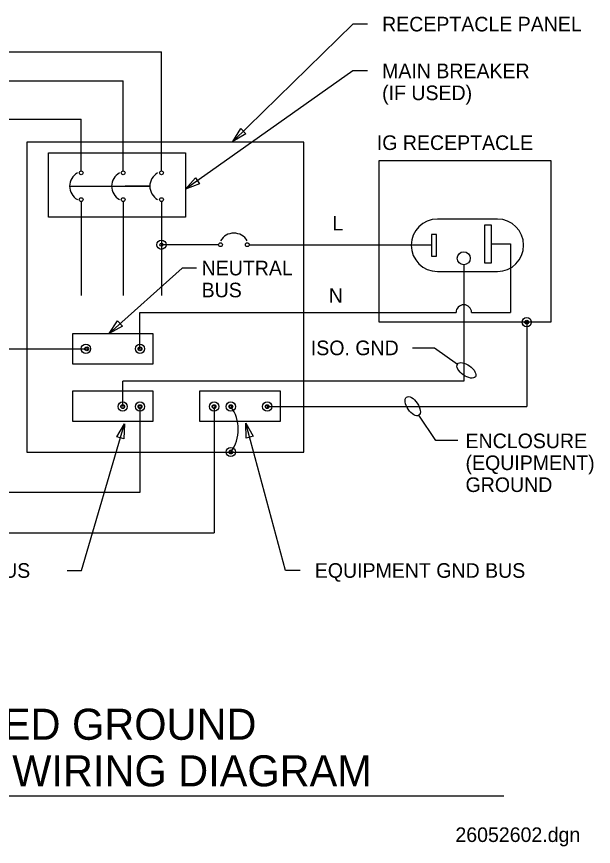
# Model space of a CAD drawing. Extents: x 10198.2 to 10245.1, y 10095.9 to 10133.7.
# Drawn here: x 10218.76 to 10245.09, y 10095.86 to 10133.72 of the extents above; entities that cross this region are included whole.
import ezdxf

# ---------------------------------------------------------------- set-up
doc = ezdxf.new("R2010")
doc.units = 0
for name, color, linetype in [('G-DETL-LINE', 7, 'Continuous'), ('G-DETL-TEXT', 7, 'Continuous'), ('G-DETL-TTXT', 7, 'Continuous')]:
    doc.layers.add(name, color=color, linetype=linetype)

msp = doc.modelspace()

# ---------------------------------------------------------------- linework, layer by layer
at = {"layer": 'G-DETL-LINE'}
for p, q in [((10212.806, 10132.117), (10225.37, 10132.117)), ((10212.806, 10132.117), (10225.37, 10132.117)), ((10225.37, 10126.681), (10225.37, 10132.117)), ((10214.725, 10130.796), (10223.625, 10130.796)), ((10214.725, 10130.796), (10223.625, 10130.796)), ((10223.625, 10126.681), (10223.625, 10130.796)), ((10223.625, 10126.681), (10223.625, 10130.796)), ((10216.47, 10129.049), (10221.706, 10129.049)), ((10216.47, 10129.049), (10221.706, 10129.049)), ((10221.706, 10126.681), (10221.706, 10129.049)), ((10221.706, 10126.681), (10221.706, 10129.049)), ((10231.867, 10127.989), (10219.225, 10127.989)), ((10219.225, 10127.989), (10219.225, 10113.856)), ((10231.867, 10127.989), (10219.225, 10127.989)), ((10219.225, 10127.989), (10219.225, 10113.856)), ((10231.867, 10113.856), (10231.867, 10127.989)), ((10231.867, 10113.856), (10231.867, 10127.989)), ((10235.305, 10127.152), (10243.142, 10127.152)), ((10235.305, 10119.781), (10235.305, 10127.152)), ((10235.305, 10127.152), (10243.142, 10127.152)), ((10235.305, 10119.781), (10235.305, 10127.152)), ((10243.142, 10127.152), (10243.142, 10119.781)), ((10243.142, 10127.152), (10243.142, 10119.781)), ((10221.177, 10125.983), (10224.841, 10125.983)), ((10221.177, 10125.983), (10222.484, 10125.983)), ((10221.177, 10125.983), (10224.841, 10125.983)), ((10221.177, 10125.983), (10222.484, 10125.983)), ((10224.841, 10125.983), (10223.715, 10125.983)), ((10224.841, 10125.983), (10223.715, 10125.983)), ((10221.706, 10125.285), (10221.706, 10120.997)), ((10221.706, 10125.285), (10221.706, 10120.997)), ((10223.625, 10125.285), (10223.625, 10120.997)), ((10223.625, 10125.285), (10223.625, 10120.997)), ((10225.37, 10125.285), (10225.37, 10120.997)), ((10240.712, 10124.486), (10237.97, 10124.486)), ((10240.712, 10124.486), (10237.97, 10124.486)), ((10240.438, 10124.212), (10240.125, 10124.212)), ((10240.125, 10124.212), (10240.125, 10122.487)), ((10240.438, 10124.212), (10240.125, 10124.212)), ((10240.125, 10124.212), (10240.125, 10122.487)), ((10240.438, 10122.487), (10240.438, 10124.212)), ((10240.438, 10122.487), (10240.438, 10124.212)), ((10237.93, 10123.781), (10237.695, 10123.781)), ((10237.695, 10123.781), (10237.695, 10122.8)), ((10237.93, 10123.781), (10237.695, 10123.781)), ((10237.695, 10123.781), (10237.695, 10122.8)), ((10237.93, 10122.8), (10237.93, 10123.781)), ((10237.93, 10122.8), (10237.93, 10123.781)), ((10227.981, 10123.315), (10225.37, 10123.315)), ((10229.377, 10123.315), (10237.695, 10123.315)), ((10240.438, 10123.349), (10241.312, 10123.349)), ((10241.312, 10123.349), (10241.312, 10120.22)), ((10237.695, 10122.8), (10237.93, 10122.8)), ((10237.695, 10122.8), (10237.93, 10122.8)), ((10240.125, 10122.487), (10240.438, 10122.487)), ((10240.125, 10122.487), (10240.438, 10122.487)), ((10237.97, 10122.095), (10240.712, 10122.095)), ((10237.97, 10122.095), (10240.712, 10122.095)), ((10239.175, 10122.402), (10239.175, 10117.092)), ((10239.175, 10122.402), (10239.175, 10117.092)), ((10224.391, 10118.568), (10224.391, 10120.22)), ((10224.391, 10120.22), (10238.82, 10120.22)), ((10239.53, 10120.22), (10241.312, 10120.22)), ((10243.142, 10119.781), (10235.305, 10119.781)), ((10243.142, 10119.781), (10235.305, 10119.781)), ((10242.049, 10119.781), (10242.049, 10115.93)), ((10242.049, 10119.781), (10242.049, 10115.93)), ((10221.318, 10119.265), (10224.982, 10119.265)), ((10221.318, 10117.869), (10221.318, 10119.265)), ((10221.318, 10119.265), (10224.982, 10119.265)), ((10221.318, 10117.869), (10221.318, 10119.265)), ((10224.982, 10119.265), (10224.982, 10117.869)), ((10224.982, 10119.265), (10224.982, 10117.869)), ((10204.262, 10118.568), (10221.921, 10118.568)), ((10224.982, 10117.869), (10221.318, 10117.869)), ((10224.982, 10117.869), (10221.318, 10117.869)), ((10239.175, 10117.092), (10223.601, 10117.092)), ((10239.175, 10117.092), (10223.601, 10117.092)), ((10223.601, 10115.93), (10223.601, 10117.092)), ((10221.318, 10115.252), (10221.318, 10116.648)), ((10221.318, 10115.252), (10221.318, 10116.648)), ((10221.318, 10116.648), (10224.982, 10116.648)), ((10224.982, 10116.648), (10224.982, 10115.252)), ((10224.982, 10116.648), (10224.982, 10115.252)), ((10227.127, 10116.648), (10230.792, 10116.648)), ((10227.127, 10115.252), (10227.127, 10116.648)), ((10230.792, 10116.648), (10230.792, 10115.252)), ((10224.391, 10115.93), (10224.391, 10112.01)), ((10224.391, 10115.93), (10224.391, 10112.01)), ((10227.774, 10115.93), (10227.774, 10110.168)), ((10227.774, 10115.93), (10227.774, 10110.168)), ((10230.2, 10115.93), (10242.049, 10115.93)), ((10230.2, 10115.93), (10242.049, 10115.93)), ((10224.982, 10115.252), (10221.318, 10115.252)), ((10230.792, 10115.252), (10227.127, 10115.252)), ((10230.792, 10115.252), (10227.127, 10115.252)), ((10219.225, 10113.856), (10231.867, 10113.856)), ((10219.225, 10113.856), (10231.867, 10113.856)), ((10224.391, 10112.01), (10204.269, 10112.01)), ((10203.479, 10110.168), (10227.774, 10110.168))]:
    msp.add_line(p, q, dxfattribs=at)
msp.add_lwpolyline([(10220.209, 10127.502), (10226.47, 10127.502), (10226.47, 10124.574), (10220.209, 10124.574)], close=True, dxfattribs=at)
msp.add_lwpolyline([(10220.209, 10127.502), (10226.47, 10127.502), (10226.47, 10124.574), (10220.209, 10124.574)], close=True, dxfattribs=at)
for centre, radius in [((10221.706, 10126.593), 0.0872), ((10221.706, 10126.593), 0.0872), ((10221.706, 10126.593), 0.0872), ((10221.706, 10126.593), 0.0872), ((10221.706, 10126.593), 0.0872), ((10221.706, 10126.593), 0.0872), ((10223.625, 10126.593), 0.0872), ((10223.625, 10126.593), 0.0872), ((10223.625, 10126.593), 0.0872), ((10223.625, 10126.593), 0.0872), ((10223.625, 10126.593), 0.0872), ((10223.625, 10126.593), 0.0872), ((10225.37, 10126.593), 0.0872), ((10225.37, 10126.593), 0.0872), ((10225.37, 10126.593), 0.0872), ((10225.37, 10126.593), 0.0872), ((10225.37, 10126.593), 0.0872), ((10225.37, 10126.593), 0.0872), ((10221.706, 10125.372), 0.0872), ((10221.706, 10125.372), 0.0872), ((10221.706, 10125.372), 0.0872), ((10221.706, 10125.372), 0.0872), ((10221.706, 10125.372), 0.0872), ((10221.706, 10125.372), 0.0872), ((10223.625, 10125.372), 0.0872), ((10223.625, 10125.372), 0.0872), ((10223.625, 10125.372), 0.0872), ((10223.625, 10125.372), 0.0872), ((10223.625, 10125.372), 0.0872), ((10223.625, 10125.372), 0.0872), ((10225.37, 10125.372), 0.0872), ((10225.37, 10125.372), 0.0872), ((10225.37, 10125.372), 0.0872), ((10225.37, 10125.372), 0.0872), ((10225.37, 10125.372), 0.0872), ((10225.37, 10125.372), 0.0872), ((10225.37, 10123.315), 0.211), ((10225.37, 10123.315), 0.211), ((10225.37, 10123.315), 0.0703), ((10225.37, 10123.315), 0.0703), ((10228.068, 10123.315), 0.0872), ((10229.289, 10123.315), 0.0872), ((10239.175, 10122.697), 0.295), ((10239.175, 10122.697), 0.295), ((10242.049, 10119.781), 0.211), ((10242.049, 10119.781), 0.211), ((10242.049, 10119.781), 0.0872), ((10242.049, 10119.781), 0.0872), ((10242.049, 10119.781), 0.0703), ((10242.049, 10119.781), 0.0703), ((10221.921, 10118.568), 0.211), ((10224.391, 10118.568), 0.211), ((10221.921, 10118.568), 0.0703), ((10221.965, 10118.568), 0.0872), ((10221.965, 10118.568), 0.0872), ((10224.391, 10118.568), 0.0872), ((10224.391, 10118.568), 0.0872), ((10224.391, 10118.568), 0.0703), ((10223.601, 10115.93), 0.211), ((10224.391, 10115.93), 0.211), ((10224.391, 10115.93), 0.211), ((10227.774, 10115.93), 0.211), ((10227.774, 10115.93), 0.211), ((10228.536, 10115.93), 0.211), ((10230.2, 10115.93), 0.211), ((10230.2, 10115.93), 0.211), ((10223.601, 10115.93), 0.0872), ((10223.601, 10115.93), 0.0872), ((10223.601, 10115.93), 0.0703), ((10224.391, 10115.93), 0.0872), ((10224.391, 10115.93), 0.0872), ((10224.391, 10115.93), 0.0703), ((10224.391, 10115.93), 0.0703), ((10227.774, 10115.93), 0.0872), ((10227.774, 10115.93), 0.0872), ((10227.774, 10115.93), 0.0703), ((10227.774, 10115.93), 0.0703), ((10228.536, 10115.93), 0.0872), ((10228.536, 10115.93), 0.0872), ((10228.536, 10115.93), 0.0703), ((10230.2, 10115.93), 0.0872), ((10230.2, 10115.93), 0.0872), ((10230.2, 10115.93), 0.0703), ((10230.2, 10115.93), 0.0703), ((10228.536, 10113.856), 0.211), ((10228.536, 10113.856), 0.0872), ((10228.536, 10113.856), 0.0872), ((10228.536, 10113.856), 0.0703)]:
    msp.add_circle(centre, radius, dxfattribs=at)
for centre, radius, start, end in [((10221.88, 10125.983), 0.703, 119.7449, 240.2551), ((10221.88, 10125.983), 0.703, 119.7449, 240.2551), ((10221.88, 10125.983), 0.703, 119.7449, 240.2551), ((10221.88, 10125.983), 0.703, 119.7449, 240.2551), ((10221.88, 10125.983), 0.703, 119.7449, 240.2551), ((10221.88, 10125.983), 0.703, 119.7449, 240.2551), ((10223.8, 10125.983), 0.703, 119.7449, 240.2551), ((10223.8, 10125.983), 0.703, 119.7449, 240.2551), ((10223.8, 10125.983), 0.703, 119.7449, 240.2551), ((10223.8, 10125.983), 0.703, 119.7449, 240.2551), ((10223.8, 10125.983), 0.703, 119.7449, 240.2551), ((10223.8, 10125.983), 0.703, 119.7449, 240.2551), ((10225.544, 10125.983), 0.703, 119.7449, 240.2551), ((10225.544, 10125.983), 0.703, 119.7449, 240.2551), ((10225.544, 10125.983), 0.703, 119.7449, 240.2551), ((10225.544, 10125.983), 0.703, 119.7449, 240.2551), ((10225.544, 10125.983), 0.703, 119.7449, 240.2551), ((10225.544, 10125.983), 0.703, 119.7449, 240.2551), ((10237.97, 10123.29), 1.196, 90, 270), ((10237.97, 10123.29), 1.196, 90, 270), ((10240.712, 10123.29), 1.196, 270, 90), ((10240.712, 10123.29), 1.196, 270, 90), ((10228.679, 10123.141), 0.703, 29.7449, 150.2551), ((10239.175, 10120.22), 0.355, 0, 180), ((10239.175, 10120.22), 0.355, 0, 180), ((10227.144, 10114.893), 1.735, 323.3128, 36.6872)]:
    msp.add_arc(centre, radius, start, end, dxfattribs=at)
at = {"layer": 'G-DETL-TEXT'}
for p, q in [((10234.112, 10133.38), (10228.635, 10128.03)), ((10234.778, 10133.38), (10234.112, 10133.38)), ((10234.112, 10131.246), (10226.475, 10125.851)), ((10234.778, 10131.246), (10234.112, 10131.246)), ((10226.311, 10122.249), (10222.979, 10119.272)), ((10226.978, 10122.249), (10226.311, 10122.249)), ((10221.727, 10108.451), (10223.685, 10115.144)), ((10231.039, 10108.451), (10229.23, 10115.181)), ((10221.06, 10108.451), (10221.727, 10108.451)), ((10231.705, 10108.451), (10231.039, 10108.451))]:
    msp.add_line(p, q, dxfattribs=at)
for points in [[(10229.229, 10128.377), (10228.635, 10128.03), (10228.996, 10128.615)], [(10227.115, 10126.1), (10226.475, 10125.851), (10226.923, 10126.372)], [(10223.587, 10119.592), (10222.979, 10119.272), (10223.365, 10119.84)], [(10223.338, 10114.551), (10223.685, 10115.144), (10223.658, 10114.457)], [(10229.242, 10114.494), (10229.23, 10115.181), (10229.564, 10114.58)]]:
    msp.add_lwpolyline(points, close=True, dxfattribs=at)
for points in [[(10236.839, 10118.611), (10237.839, 10118.611), (10238.887, 10117.871)], [(10238.902, 10114.389), (10237.902, 10114.389), (10237.123, 10115.535)]]:
    msp.add_lwpolyline(points, dxfattribs=at)
for centre, major_axis in [((10239.295, 10117.582), (0.408, -0.289)), ((10236.842, 10115.948), (-0.281, 0.414))]:
    msp.add_ellipse(centre, major_axis=major_axis, ratio=0.5, dxfattribs=at)
at = {"layer": 'G-DETL-TTXT'}
msp.add_line((10202.478, 10098.17), (10241.002, 10098.17), dxfattribs=at)

# ---------------------------------------------------------------- texts
at = {"layer": 'G-DETL-TEXT'}
for s, height, p in [('RECEPTACLE PANEL', 0.66667, (10235.445, 10133.047)), ('MAIN BREAKER', 0.66667, (10235.445, 10130.912)), ('(IF USED)', 0.6667, (10235.445, 10129.912)), ('IG RECEPTACLE', 0.66667, (10235.204, 10127.638)), ('L', 0.667, (10233.171, 10123.965)), ('NEUTRAL ', 0.6667, (10227.205, 10121.916)), ('BUS', 0.6667, (10227.205, 10120.916)), ('N', 0.667, (10233.01, 10120.664)), ('ISO. GND', 0.6667, (10232.192, 10118.275)), ('ENCLOSURE', 0.6667, (10239.255, 10114.033)), ('(EQUIPMENT)', 0.66667, (10239.255, 10113.033)), ('GROUND', 0.6667, (10239.255, 10112.033)), ('ISOLATED GND BUS', 0.66667, (10210.661, 10108.118)), ('EQUIPMENT GND BUS', 0.66667, (10232.372, 10108.118))]:
    msp.add_text(s, height=height, dxfattribs=at).set_placement(p)
at = {"layer": 'G-DETL-TTXT'}
for s, height, p in [('ISOLATED GROUND', 1.41667, (10211.393, 10100.728)), ('RECEPTACLE WIRING DIAGRAM', 1.41667, (10205.4, 10098.603)), ('26052602.dgn', 0.66667, (10238.792, 10096.064))]:
    msp.add_text(s, height=height, dxfattribs=at).set_placement(p)

doc.saveas('drawing.dxf')
